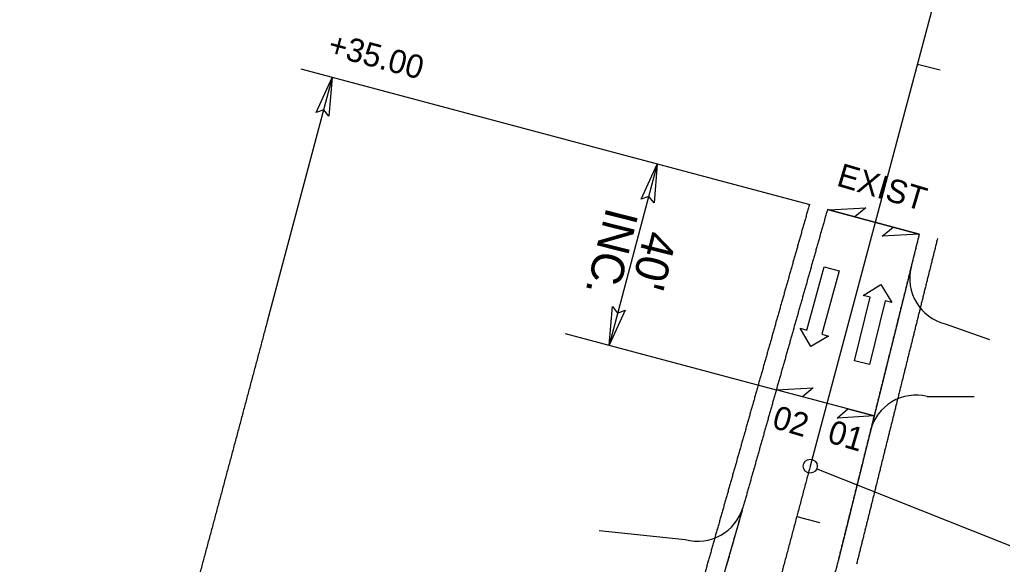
# Model space of a CAD drawing. Extents: x 1778969 to 1790720, y 807089 to 817794.
# Drawn here: x 1782827.8 to 1783037.6, y 815239.3 to 815355.7 of the extents above; entities that cross this region are included whole.
import ezdxf

# ---------------------------------------------------------------- set-up
doc = ezdxf.new("R2010")
doc.units = 0
for name, color, linetype in [('Prop Dimension', 7, 'Continuous'), ('Prop Dimension Text', 7, 'Continuous'), ('Prop EOT', 7, 'Continuous'), ('Prop Horizontal Alignment', 7, 'Continuous'), ('Prop Horizontal Alignment Station Label', 7, 'Continuous'), ('Prop Horizontal Alignment Tick Small', 7, 'Continuous'), ('Prop Lane Arrow CELL', 7, 'Continuous'), ('Prop Paved Shoulder', 7, 'Continuous'), ('Prop Superelevation  Arrow CELL', 7, 'Continuous'), ('Prop Superelevation Label', 7, 'Continuous'), ('Prop Terminator CELL', 7, 'Continuous')]:
    doc.layers.add(name, color=color, linetype=linetype)

msp = doc.modelspace()

# ---------------------------------------------------------------- linework, layer by layer
at = {"layer": 'Prop Dimension'}
for p, q in [((1782996.58, 815316.08), (1782887.9, 815345.06)), ((1782894.54, 815343.29), (1782880.65, 815291.21)), ((1782963.95, 815324.78), (1782953.65, 815286.13)), ((1783019.89, 815309.86), (1783000.28, 815315.09)), ((1782944.24, 815288.63), (1782989.36, 815276.6))]:
    msp.add_line(p, q, dxfattribs=at)
msp.add_spline([(1782880.65, 815291.21), (1782879.95, 815288.6), (1782879.26, 815285.99), (1782878.56, 815283.39), (1782877.87, 815280.78), (1782877.17, 815278.18), (1782876.48, 815275.58), (1782875.78, 815272.98), (1782875.09, 815270.38), (1782874.4, 815267.79), (1782873.7, 815265.19), (1782873.01, 815262.6), (1782872.31, 815260.01), (1782871.62, 815257.42), (1782870.93, 815254.84), (1782870.23, 815252.25), (1782869.54, 815249.67), (1782868.85, 815247.09), (1782868.15, 815244.51), (1782867.46, 815241.94), (1782866.76, 815239.36), (1782866.07, 815236.79), (1782865.37, 815234.22), (1782864.68, 815231.65), (1782863.98, 815229.09), (1782863.28, 815226.52), (1782862.59, 815223.96), (1782861.89, 815221.4), (1782861.19, 815218.85), (1782860.49, 815216.29), (1782859.79, 815213.74), (1782859.09, 815211.19), (1782858.39, 815208.64), (1782857.69, 815206.09), (1782856.99, 815203.55), (1782856.28, 815201), (1782855.58, 815198.46), (1782854.87, 815195.93), (1782854.17, 815193.39), (1782853.46, 815190.86), (1782852.75, 815188.33), (1782852.04, 815185.8), (1782851.33, 815183.27), (1782850.62, 815180.75), (1782849.91, 815178.22), (1782849.19, 815175.7), (1782848.48, 815173.19), (1782847.76, 815170.67), (1782847.04, 815168.16), (1782846.32, 815165.65), (1782845.6, 815163.14), (1782844.88, 815160.63), (1782844.16, 815158.13), (1782843.43, 815155.63), (1782842.71, 815153.13), (1782841.98, 815150.64), (1782841.25, 815148.14), (1782840.52, 815145.65), (1782839.78, 815143.16), (1782839.05, 815140.68), (1782838.31, 815138.19), (1782837.57, 815135.71), (1782836.83, 815133.23), (1782836.09, 815130.76), (1782835.34, 815128.28), (1782834.6, 815125.81), (1782833.85, 815123.34), (1782833.1, 815120.88), (1782832.35, 815118.41), (1782831.59, 815115.95), (1782830.84, 815113.49), (1782830.08, 815111.04), (1782829.32, 815108.58), (1782828.56, 815106.13), (1782827.77, 815103.62)], degree=3, dxfattribs=at)
at = {"layer": 'Prop EOT'}
for p, q in [((1783000.28, 815315.09), (1783019.89, 815309.86)), ((1783019.89, 815309.86), (1783017.9, 815301.84)), ((1783018.14, 815302.81), (1783002.61, 815240.29)), ((1783025.43, 815290.69), (1783034.86, 815287.33)), ((1783021.58, 815275.16), (1783031.61, 815275.15)), ((1782981.48, 815248.81), (1782960.94, 815177.35)), ((1782951.53, 815246.55), (1782969.91, 815244.66))]:
    msp.add_line(p, q, dxfattribs=at)
for centre, start, end in [((1783027.85, 815300.4), 166.0436, 256.0147), ((1783019.17, 815265.46), 76.0147, 166.0436), ((1782972.63, 815254.28), 254.2047, 344.1607)]:
    msp.add_arc(centre, 10, start, end, dxfattribs=at)
for points in [[(1783000.28, 815315.09), (1783000.01, 815314.16), (1782999.75, 815313.22), (1782999.49, 815312.29), (1782999.22, 815311.36), (1782998.96, 815310.43), (1782998.69, 815309.5), (1782998.43, 815308.57), (1782998.16, 815307.63), (1782997.9, 815306.7), (1782997.64, 815305.77), (1782997.37, 815304.84), (1782997.11, 815303.91), (1782996.84, 815302.97), (1782996.58, 815302.04), (1782996.31, 815301.11), (1782996.05, 815300.18), (1782995.79, 815299.25), (1782995.52, 815298.32), (1782995.26, 815297.38), (1782994.99, 815296.45), (1782994.73, 815295.52), (1782994.46, 815294.59), (1782994.2, 815293.66), (1782993.93, 815292.72), (1782993.67, 815291.79), (1782993.41, 815290.86), (1782993.14, 815289.93), (1782992.88, 815289), (1782992.61, 815288.07), (1782992.35, 815287.13), (1782992.08, 815286.2), (1782991.82, 815285.27), (1782991.56, 815284.34), (1782991.29, 815283.41), (1782991.03, 815282.47), (1782990.76, 815281.54), (1782990.5, 815280.61), (1782990.23, 815279.68), (1782989.97, 815278.75), (1782989.71, 815277.82), (1782989.44, 815276.88), (1782989.18, 815275.95), (1782988.91, 815275.02), (1782988.65, 815274.09), (1782988.38, 815273.16), (1782988.12, 815272.22), (1782987.85, 815271.29), (1782987.59, 815270.36), (1782987.33, 815269.43), (1782987.06, 815268.5), (1782986.8, 815267.57), (1782986.53, 815266.63), (1782986.27, 815265.7), (1782986, 815264.77), (1782985.74, 815263.84), (1782985.48, 815262.91), (1782985.21, 815261.97), (1782984.95, 815261.04), (1782984.68, 815260.11), (1782984.42, 815259.18), (1782984.15, 815258.25), (1782983.89, 815257.32), (1782983.63, 815256.38), (1782983.36, 815255.45), (1782983.1, 815254.52), (1782982.83, 815253.59), (1782982.57, 815252.66), (1782982.3, 815251.73), (1782982.04, 815250.79), (1782981.77, 815249.86), (1782981.51, 815248.93), (1782981.25, 815248), (1782980.98, 815247.07), (1782980.72, 815246.14)], [(1783019.89, 815309.86), (1783019.66, 815308.92), (1783019.43, 815307.98), (1783019.19, 815307.04), (1783018.96, 815306.1), (1783018.73, 815305.16), (1783018.49, 815304.22), (1783018.26, 815303.28), (1783018.03, 815302.34), (1783017.79, 815301.4), (1783017.56, 815300.46), (1783017.33, 815299.52), (1783017.09, 815298.58), (1783016.86, 815297.64), (1783016.62, 815296.7), (1783016.39, 815295.76), (1783016.16, 815294.82), (1783015.92, 815293.88), (1783015.69, 815292.94), (1783015.46, 815292), (1783015.22, 815291.06), (1783014.99, 815290.12), (1783014.76, 815289.18), (1783014.52, 815288.24), (1783014.29, 815287.3), (1783014.06, 815286.36), (1783013.82, 815285.42), (1783013.59, 815284.48), (1783013.35, 815283.54), (1783013.12, 815282.6), (1783012.89, 815281.66), (1783012.65, 815280.72), (1783012.42, 815279.78), (1783012.19, 815278.84), (1783011.95, 815277.9), (1783011.72, 815276.96), (1783011.49, 815276.02), (1783011.25, 815275.08), (1783011.02, 815274.14), (1783010.78, 815273.2), (1783010.55, 815272.26), (1783010.32, 815271.32), (1783010.08, 815270.38), (1783009.85, 815269.44), (1783009.62, 815268.5), (1783009.38, 815267.56), (1783009.15, 815266.62), (1783008.92, 815265.68), (1783008.68, 815264.74), (1783008.45, 815263.8), (1783008.22, 815262.86), (1783007.98, 815261.92), (1783007.75, 815260.98), (1783007.51, 815260.04), (1783007.28, 815259.1), (1783007.05, 815258.16), (1783006.81, 815257.22), (1783006.58, 815256.28), (1783006.35, 815255.34), (1783006.11, 815254.4), (1783005.88, 815253.46), (1783005.65, 815252.52), (1783005.41, 815251.58), (1783005.18, 815250.63), (1783004.94, 815249.69), (1783004.71, 815248.75), (1783004.48, 815247.81), (1783004.24, 815246.87), (1783004.01, 815245.93), (1783003.78, 815244.99), (1783003.54, 815244.05), (1783003.31, 815243.11), (1783003.07, 815242.17), (1783002.84, 815241.23), (1783002.61, 815240.29)], [(1782980.72, 815246.14), (1782980.45, 815245.21), (1782980.19, 815244.28), (1782979.92, 815243.34), (1782979.66, 815242.41), (1782979.39, 815241.48), (1782979.13, 815240.55), (1782978.86, 815239.62), (1782978.6, 815238.69), (1782978.33, 815237.76), (1782978.07, 815236.83), (1782977.8, 815235.9), (1782977.54, 815234.96), (1782977.27, 815234.03), (1782977.01, 815233.1), (1782976.74, 815232.17), (1782976.48, 815231.24), (1782976.21, 815230.31), (1782975.95, 815229.38), (1782975.68, 815228.45), (1782975.42, 815227.52), (1782975.15, 815226.59), (1782974.89, 815225.66), (1782974.62, 815224.73), (1782974.36, 815223.8), (1782974.09, 815222.87), (1782973.82, 815221.94), (1782973.56, 815221.01), (1782973.29, 815220.08), (1782973.03, 815219.15), (1782972.76, 815218.22), (1782972.49, 815217.29), (1782972.23, 815216.36), (1782971.96, 815215.43), (1782971.69, 815214.5), (1782971.43, 815213.57), (1782971.16, 815212.64), (1782970.89, 815211.71), (1782970.63, 815210.78), (1782970.36, 815209.85), (1782970.09, 815208.92), (1782969.83, 815207.99), (1782969.56, 815207.06), (1782969.29, 815206.13), (1782969.02, 815205.2), (1782968.76, 815204.27), (1782968.49, 815203.34), (1782968.22, 815202.41), (1782967.95, 815201.48), (1782967.68, 815200.55), (1782967.42, 815199.63), (1782967.15, 815198.7), (1782966.88, 815197.77), (1782966.61, 815196.84), (1782966.34, 815195.91), (1782966.07, 815194.98), (1782965.8, 815194.05), (1782965.53, 815193.13), (1782965.27, 815192.2), (1782965, 815191.27), (1782964.73, 815190.34), (1782964.46, 815189.41), (1782964.19, 815188.48), (1782963.92, 815187.56), (1782963.65, 815186.63), (1782963.38, 815185.7), (1782963.11, 815184.77), (1782962.84, 815183.84), (1782962.57, 815182.92), (1782962.29, 815181.99), (1782962.02, 815181.06), (1782961.75, 815180.13), (1782961.48, 815179.21), (1782961.21, 815178.28), (1782960.94, 815177.35)], [(1783002.61, 815240.29), (1783002.37, 815239.35), (1783002.14, 815238.41), (1783001.9, 815237.47), (1783001.67, 815236.53), (1783001.44, 815235.59), (1783001.2, 815234.65), (1783000.97, 815233.71), (1783000.73, 815232.77), (1783000.5, 815231.83), (1783000.26, 815230.89), (1783000.03, 815229.95), (1782999.8, 815229.01), (1782999.56, 815228.07), (1782999.33, 815227.13), (1782999.09, 815226.19), (1782998.86, 815225.25), (1782998.62, 815224.3), (1782998.39, 815223.36), (1782998.15, 815222.42), (1782997.92, 815221.48), (1782997.68, 815220.54), (1782997.45, 815219.6), (1782997.21, 815218.66), (1782996.97, 815217.72), (1782996.74, 815216.78), (1782996.5, 815215.84), (1782996.27, 815214.9), (1782996.03, 815213.96), (1782995.8, 815213.02), (1782995.56, 815212.08), (1782995.32, 815211.14), (1782995.09, 815210.2), (1782994.85, 815209.26), (1782994.61, 815208.32), (1782994.38, 815207.38), (1782994.14, 815206.43), (1782993.9, 815205.49), (1782993.67, 815204.55), (1782993.43, 815203.61), (1782993.19, 815202.67), (1782992.96, 815201.73), (1782992.72, 815200.79), (1782992.48, 815199.85), (1782992.24, 815198.91), (1782992.01, 815197.97), (1782991.77, 815197.03), (1782991.53, 815196.09), (1782991.29, 815195.15), (1782991.05, 815194.21), (1782990.82, 815193.27), (1782990.58, 815192.33), (1782990.34, 815191.39), (1782990.1, 815190.45), (1782989.86, 815189.51), (1782989.62, 815188.57), (1782989.38, 815187.62), (1782989.14, 815186.68), (1782988.9, 815185.74), (1782988.66, 815184.8), (1782988.42, 815183.86), (1782988.18, 815182.92), (1782987.94, 815181.98), (1782987.7, 815181.04), (1782987.46, 815180.1), (1782987.22, 815179.16), (1782986.98, 815178.22), (1782986.74, 815177.28), (1782986.5, 815176.34), (1782986.26, 815175.4), (1782986.02, 815174.46), (1782985.78, 815173.52), (1782985.53, 815172.58), (1782985.29, 815171.64), (1782985.05, 815170.7)]]:
    msp.add_spline(points, degree=3, dxfattribs=at)
at = {"layer": 'Prop Horizontal Alignment'}
msp.add_line((1783199.88, 816022.55), (1782996.6, 815260.29), dxfattribs=at)
msp.add_spline([(1782996.6, 815260.29), (1782995.9, 815257.68), (1782995.2, 815255.07), (1782994.51, 815252.46), (1782993.81, 815249.85), (1782993.11, 815247.23), (1782992.42, 815244.62), (1782991.72, 815242.01), (1782991.02, 815239.4), (1782990.32, 815236.79), (1782989.62, 815234.18), (1782988.93, 815231.57), (1782988.23, 815228.96), (1782987.53, 815226.35), (1782986.83, 815223.74), (1782986.13, 815221.13), (1782985.43, 815218.52), (1782984.72, 815215.91), (1782984.02, 815213.3), (1782983.32, 815210.69), (1782982.61, 815208.08), (1782981.91, 815205.47), (1782981.2, 815202.86), (1782980.49, 815200.25), (1782979.79, 815197.64), (1782979.08, 815195.03), (1782978.37, 815192.43), (1782977.66, 815189.82), (1782976.95, 815187.21), (1782976.23, 815184.6), (1782975.52, 815182), (1782974.8, 815179.39), (1782974.09, 815176.79), (1782973.37, 815174.18), (1782972.65, 815171.57), (1782971.93, 815168.97), (1782971.21, 815166.37), (1782970.48, 815163.76), (1782969.76, 815161.16), (1782969.03, 815158.55), (1782968.3, 815155.95), (1782967.57, 815153.35), (1782966.84, 815150.75), (1782966.11, 815148.15), (1782965.37, 815145.55), (1782964.64, 815142.95), (1782963.9, 815140.35), (1782963.16, 815137.75), (1782962.41, 815135.15), (1782961.67, 815132.55), (1782960.92, 815129.95), (1782960.17, 815127.35), (1782959.42, 815124.76), (1782958.67, 815122.16), (1782957.92, 815119.57), (1782957.16, 815116.97), (1782956.4, 815114.38), (1782955.64, 815111.79), (1782954.87, 815109.19), (1782954.11, 815106.6), (1782953.34, 815104.01), (1782952.57, 815101.42), (1782951.79, 815098.83), (1782951.02, 815096.24), (1782950.24, 815093.65), (1782949.46, 815091.07), (1782948.67, 815088.48), (1782947.89, 815085.89), (1782947.1, 815083.31), (1782946.31, 815080.73), (1782945.51, 815078.14), (1782944.71, 815075.56), (1782943.91, 815072.98), (1782943.11, 815070.4), (1782942.3, 815067.82)], degree=3, dxfattribs=at)
at = {"layer": 'Prop Horizontal Alignment Station Label'}
msp.add_line((1782997.99, 815259.74), (1783313.77, 815133.98), dxfattribs=at)
msp.add_circle((1782996.6, 815260.29), 1.5, dxfattribs=at)
at = {"layer": 'Prop Horizontal Alignment Tick Small'}
for p, q in [((1783019.5, 815346.18), (1783024.33, 815344.9)), ((1782993.73, 815249.56), (1782998.57, 815248.27))]:
    msp.add_line(p, q, dxfattribs=at)
at = {"layer": 'Prop Lane Arrow CELL'}
for p, q in [((1782995.91, 815289.36), (1782999.6, 815302.86)), ((1782999.6, 815302.86), (1783002.79, 815301.99)), ((1783002.79, 815301.99), (1782999.09, 815288.48)), ((1783007.93, 815296.77), (1783011.7, 815299.09)), ((1783011.7, 815299.09), (1783014.05, 815295.27)), ((1783006.05, 815282.82), (1783009.39, 815296.42)), ((1783009.39, 815296.42), (1783007.93, 815296.77)), ((1783012.6, 815295.63), (1783009.26, 815282.03)), ((1783014.05, 815295.27), (1783012.6, 815295.63)), ((1782996.72, 815285.87), (1782994.46, 815289.75)), ((1782994.46, 815289.75), (1782995.91, 815289.36)), ((1783000.54, 815288.09), (1782996.72, 815285.87)), ((1782999.09, 815288.48), (1783000.54, 815288.09)), ((1783009.26, 815282.03), (1783006.05, 815282.82))]:
    msp.add_line(p, q, dxfattribs=at)
at = {"layer": 'Prop Paved Shoulder'}
for points in [[(1782996.43, 815316.18), (1782996.17, 815315.25), (1782995.9, 815314.32), (1782995.64, 815313.38), (1782995.37, 815312.45), (1782995.11, 815311.52), (1782994.84, 815310.59), (1782994.58, 815309.66), (1782994.32, 815308.73), (1782994.05, 815307.79), (1782993.79, 815306.86), (1782993.52, 815305.93), (1782993.26, 815305), (1782992.99, 815304.07), (1782992.73, 815303.13), (1782992.47, 815302.2), (1782992.2, 815301.27), (1782991.94, 815300.34), (1782991.67, 815299.41), (1782991.41, 815298.48), (1782991.14, 815297.54), (1782990.88, 815296.61), (1782990.62, 815295.68), (1782990.35, 815294.75), (1782990.09, 815293.82), (1782989.82, 815292.88), (1782989.56, 815291.95), (1782989.29, 815291.02), (1782989.03, 815290.09), (1782988.76, 815289.16), (1782988.5, 815288.23), (1782988.24, 815287.29), (1782987.97, 815286.36), (1782987.71, 815285.43), (1782987.44, 815284.5), (1782987.18, 815283.57), (1782986.91, 815282.63), (1782986.65, 815281.7), (1782986.39, 815280.77), (1782986.12, 815279.84), (1782985.86, 815278.91), (1782985.59, 815277.98), (1782985.33, 815277.04), (1782985.06, 815276.11), (1782984.8, 815275.18), (1782984.54, 815274.25), (1782984.27, 815273.32), (1782984.01, 815272.38), (1782983.74, 815271.45), (1782983.48, 815270.52), (1782983.21, 815269.59), (1782982.95, 815268.66), (1782982.69, 815267.73), (1782982.42, 815266.79), (1782982.16, 815265.86), (1782981.89, 815264.93), (1782981.63, 815264), (1782981.36, 815263.07), (1782981.1, 815262.13), (1782980.83, 815261.2), (1782980.57, 815260.27), (1782980.31, 815259.34), (1782980.04, 815258.41), (1782979.78, 815257.48), (1782979.51, 815256.54), (1782979.25, 815255.61), (1782978.98, 815254.68), (1782978.72, 815253.75), (1782978.46, 815252.82), (1782978.19, 815251.89), (1782977.93, 815250.96), (1782977.66, 815250.02), (1782977.4, 815249.09), (1782977.13, 815248.16), (1782976.87, 815247.23)], [(1783023.78, 815308.89), (1783023.54, 815307.95), (1783023.31, 815307.01), (1783023.08, 815306.07), (1783022.84, 815305.13), (1783022.61, 815304.19), (1783022.38, 815303.25), (1783022.14, 815302.31), (1783021.91, 815301.37), (1783021.67, 815300.43), (1783021.44, 815299.49), (1783021.21, 815298.55), (1783020.97, 815297.61), (1783020.74, 815296.67), (1783020.51, 815295.73), (1783020.27, 815294.79), (1783020.04, 815293.85), (1783019.81, 815292.91), (1783019.57, 815291.97), (1783019.34, 815291.03), (1783019.11, 815290.09), (1783018.87, 815289.15), (1783018.64, 815288.21), (1783018.4, 815287.27), (1783018.17, 815286.33), (1783017.94, 815285.39), (1783017.7, 815284.45), (1783017.47, 815283.51), (1783017.24, 815282.57), (1783017, 815281.63), (1783016.77, 815280.69), (1783016.54, 815279.75), (1783016.3, 815278.81), (1783016.07, 815277.87), (1783015.83, 815276.93), (1783015.6, 815275.99), (1783015.37, 815275.05), (1783015.13, 815274.11), (1783014.9, 815273.17), (1783014.67, 815272.23), (1783014.43, 815271.29), (1783014.2, 815270.35), (1783013.97, 815269.41), (1783013.73, 815268.47), (1783013.5, 815267.53), (1783013.27, 815266.59), (1783013.03, 815265.65), (1783012.8, 815264.71), (1783012.56, 815263.77), (1783012.33, 815262.83), (1783012.1, 815261.89), (1783011.86, 815260.95), (1783011.63, 815260.01), (1783011.4, 815259.07), (1783011.16, 815258.13), (1783010.93, 815257.19), (1783010.7, 815256.25), (1783010.46, 815255.31), (1783010.23, 815254.37), (1783010, 815253.43), (1783009.76, 815252.49), (1783009.53, 815251.55), (1783009.29, 815250.61), (1783009.06, 815249.67), (1783008.83, 815248.73), (1783008.59, 815247.79), (1783008.36, 815246.85), (1783008.13, 815245.91), (1783007.89, 815244.97), (1783007.66, 815244.03), (1783007.42, 815243.09), (1783007.19, 815242.15), (1783006.96, 815241.21), (1783006.72, 815240.27), (1783006.49, 815239.33)], [(1782976.87, 815247.23), (1782976.6, 815246.3), (1782976.34, 815245.37), (1782976.08, 815244.44), (1782975.81, 815243.51), (1782975.55, 815242.58), (1782975.28, 815241.64), (1782975.02, 815240.71), (1782974.75, 815239.78), (1782974.49, 815238.85), (1782974.22, 815237.92), (1782973.96, 815236.99), (1782973.69, 815236.06), (1782973.43, 815235.13), (1782973.16, 815234.2), (1782972.9, 815233.27), (1782972.63, 815232.34), (1782972.37, 815231.41), (1782972.1, 815230.48), (1782971.84, 815229.55), (1782971.57, 815228.62), (1782971.31, 815227.69), (1782971.04, 815226.76), (1782970.77, 815225.83), (1782970.51, 815224.9), (1782970.24, 815223.97), (1782969.98, 815223.04), (1782969.71, 815222.11), (1782969.45, 815221.18), (1782969.18, 815220.25), (1782968.91, 815219.32), (1782968.65, 815218.39), (1782968.38, 815217.46), (1782968.12, 815216.53), (1782967.85, 815215.6), (1782967.58, 815214.67), (1782967.32, 815213.74), (1782967.05, 815212.81), (1782966.78, 815211.88), (1782966.52, 815210.95), (1782966.25, 815210.02), (1782965.98, 815209.09), (1782965.71, 815208.17), (1782965.45, 815207.24), (1782965.18, 815206.31), (1782964.91, 815205.38), (1782964.64, 815204.45), (1782964.38, 815203.52), (1782964.11, 815202.59), (1782963.84, 815201.66), (1782963.57, 815200.74), (1782963.3, 815199.81), (1782963.04, 815198.88), (1782962.77, 815197.95), (1782962.5, 815197.02), (1782962.23, 815196.09), (1782961.96, 815195.17), (1782961.69, 815194.24), (1782961.42, 815193.31), (1782961.15, 815192.38), (1782960.89, 815191.46), (1782960.62, 815190.53), (1782960.35, 815189.6), (1782960.08, 815188.67), (1782959.81, 815187.75), (1782959.54, 815186.82), (1782959.27, 815185.89), (1782959, 815184.96), (1782958.73, 815184.04), (1782958.46, 815183.11), (1782958.18, 815182.18), (1782957.91, 815181.26), (1782957.64, 815180.33), (1782957.37, 815179.4), (1782957.1, 815178.48)]]:
    msp.add_spline(points, degree=3, dxfattribs=at)
at = {"layer": 'Prop Superelevation  Arrow CELL'}
for p, q in [((1783000.56, 815315.01), (1783010.74, 815312.3)), ((1783019.89, 815309.86), (1783010.56, 815312.35)), ((1783010.25, 815271.03), (1782989.36, 815276.6))]:
    msp.add_line(p, q, dxfattribs=at)
for points in [[(1783000.56, 815315.01), (1783008.45, 815315.49), (1783006.14, 815313.52)], [(1783019.89, 815309.86), (1783012, 815309.38), (1783014.31, 815311.35)], [(1782989.36, 815276.6), (1782997.26, 815277.03), (1782994.94, 815275.07)], [(1783010.25, 815271.03), (1783002.36, 815270.56), (1783004.66, 815272.53)]]:
    msp.add_lwpolyline(points, close=True, dxfattribs=at)
at = {"layer": 'Prop Terminator CELL'}
for points in [[(1782891.1, 815335.82), (1782894.54, 815343.29), (1782893.83, 815335.05), (1782892.7, 815336.42)], [(1782960.52, 815317.31), (1782963.95, 815324.78), (1782963.25, 815316.54), (1782962.12, 815317.91)], [(1782957.08, 815293.59), (1782953.65, 815286.13), (1782954.35, 815294.37), (1782955.48, 815293)]]:
    msp.add_lwpolyline(points, close=True, dxfattribs=at)

# ---------------------------------------------------------------- texts
at = {"layer": 'Prop Dimension Text'}
for s, height, rotation, p in [('+35.00', 5, 345.0319, (1782893.32, 815348.17)), ('INC.', 7, 255.8503, (1782953.16, 815315.79)), ("40'", 7, 255.8503, (1782961.38, 815310.89))]:
    msp.add_text(s, height=height, rotation=rotation, dxfattribs=at).set_placement(p)
at = {"layer": 'Prop Superelevation Label'}
for s, p in [('EXIST', (1783002.01, 815320.27)), ('02', (1782988.21, 815268.57)), ('01', (1783000.02, 815265.48))]:
    msp.add_text(s, height=5, rotation=343.4339, dxfattribs=at).set_placement(p)

doc.saveas('drawing.dxf')
